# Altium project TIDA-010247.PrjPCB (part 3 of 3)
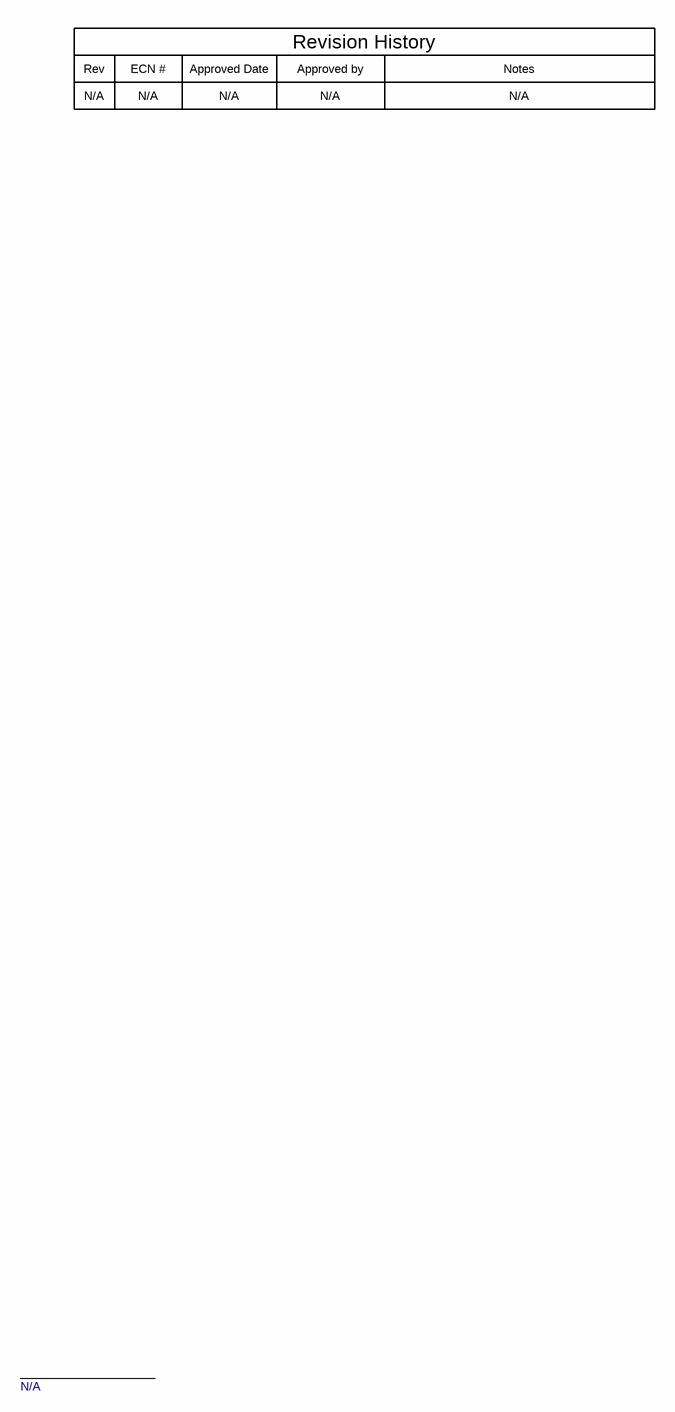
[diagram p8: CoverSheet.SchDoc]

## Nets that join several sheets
GND: High level sch (P7.2 R217.1), Monitor and Cell balancing (37 pins), Aux power (12 pins), MCU and Communication (28 pins), High-side MOSFETs and driver (D26.2 D27.2)
UP_GND: Monitor and Cell balancing (35 pins), High-side MOSFETs and driver (D18.2 D20.2 D23.2)
5V: Monitor and Cell balancing (R120.2), Aux power (R216.2), MCU and Communication (6 pins)
485A: High level sch (P6.1), MCU and Communication (L3.1)
485B: High level sch (P6.2), MCU and Communication (L4.1)
BAT_IN: High level sch (R218.1), Monitor and Cell balancing (D9.2 D12.2), Aux power (D48.2)
BOT_ALERT: Monitor and Cell balancing (U1.25), MCU and Communication (R182.2)
BOT_CB: Monitor and Cell balancing (R113.1), MCU and Communication (U5.7)
BOT_DDSG: High level sch (D49.1), MCU and Communication (D46.1), High-side MOSFETs and driver (R162.1)
BOT_LD: Monitor and Cell balancing (U1.41), High-side MOSFETs and driver (D26.1 D32.2 R169.1)
BOT_PACK: Monitor and Cell balancing (U1.42), High-side MOSFETs and driver (D27.1 R170.1)
BOT_SHUT: Monitor and Cell balancing (C39.1 R110.2 U1.33), MCU and Communication (R183.1)
BOT_WAKE: Monitor and Cell balancing (R87.1), MCU and Communication (U5.36)
BOTAFE_DDSG: High level sch (D49.2), Monitor and Cell balancing (R128.1 U1.32)
CANH: High level sch (P5.2), MCU and Communication (L2.1)
CANL: High level sch (P5.1), MCU and Communication (L1.1)
Cell0: High level sch (P3.1), Monitor and Cell balancing (Q1.2 R21.1)
Cell1: High level sch (P3.2), Monitor and Cell balancing (Q2.2 R1.1 R2.1 R23.1)
Cell2: High level sch (P3.3), Monitor and Cell balancing (Q3.2 R3.1 R4.1 R25.1)
Cell3: High level sch (P3.4), Monitor and Cell balancing (Q4.2 R5.1 R6.1 R27.1)
Cell4: High level sch (P3.5), Monitor and Cell balancing (Q5.2 R7.1 R8.1 R29.1)
Cell5: High level sch (P3.6), Monitor and Cell balancing (Q6.2 R9.1 R10.1 R31.1)
Cell6: High level sch (P3.7), Monitor and Cell balancing (Q7.2 R11.1 R12.1 R33.1)
Cell7: High level sch (P3.8), Monitor and Cell balancing (Q8.2 R13.1 R14.1 R35.1)
Cell8: High level sch (P3.9), Monitor and Cell balancing (Q9.2 R15.1 R16.1 R37.1)
Cell9: High level sch (P3.10), Monitor and Cell balancing (Q10.2 R17.1 R18.1 R39.1)
Cell10: High level sch (P3.11), Monitor and Cell balancing (6 pins)
Cell10B: High level sch (P4.1), Monitor and Cell balancing (Q11.2 R62.1 R63.2 R64.1)
Cell11: High level sch (P4.2), Monitor and Cell balancing (Q12.2 R42.1 R43.1 R66.1)
Cell12: High level sch (P4.3), Monitor and Cell balancing (Q13.2 R44.1 R45.1 R68.1)
Cell13: High level sch (P4.4), Monitor and Cell balancing (Q14.2 R46.1 R47.1 R70.1)
Cell14: High level sch (P4.5), Monitor and Cell balancing (Q15.2 R48.1 R49.1 R72.1)
Cell15: High level sch (P4.6), Monitor and Cell balancing (Q16.2 R50.1 R51.1 R74.1)
Cell16: High level sch (P4.7), Monitor and Cell balancing (Q17.2 R52.1 R53.1 R76.1)
Cell17: High level sch (P4.8), Monitor and Cell balancing (Q18.2 R54.1 R55.1 R78.1)
Cell18: High level sch (P4.9), Monitor and Cell balancing (Q19.2 R56.1 R57.1 R80.1)
Cell19: High level sch (P4.10), Monitor and Cell balancing (Q20.2 R58.1 R59.1 R82.1)
Cell20: High level sch (P4.11 R218.2), Monitor and Cell balancing (R60.1 R61.1 R84.1)
CFETOFF: Monitor and Cell balancing (U1.29), MCU and Communication (R185.2)
Current+: High level sch (5 pins), Monitor and Cell balancing (R103.1), High-side MOSFETs and driver (5 pins)
DET: High level sch (P7.1), MCU and Communication (D38.1)
DFETOFF: Monitor and Cell balancing (U1.30), MCU and Communication (R181.2)
PACK-: High level sch (R219.2 R220.2 R221.2 R222.2), Monitor and Cell balancing (R102.1), High-side MOSFETs and driver (C60.2 D37.2 R173.1)
PWR_EN: Aux power (U9.3), MCU and Communication (R196.1)
SCL: Monitor and Cell balancing (U1.26 U3.3), MCU and Communication (R195.1)
SDA: Monitor and Cell balancing (U1.27 U3.2), MCU and Communication (R192.1)
TOP_ALERT: Monitor and Cell balancing (D15.1 R123.2 R124.2), MCU and Communication (R186.2)
TOP_CHG: Monitor and Cell balancing (U2.45), High-side MOSFETs and driver (R139.1)
TOP_CP1: Monitor and Cell balancing (C29.1 U2.46), High-side MOSFETs and driver (R149.1)
TOP_DSG: Monitor and Cell balancing (U2.43), High-side MOSFETs and driver (R147.2)
TOP_LD: Monitor and Cell balancing (U2.41), High-side MOSFETs and driver (6 pins)
TOP_PDSG: Monitor and Cell balancing (U2.39), High-side MOSFETs and driver (D18.1 R145.1)
TOP_SHUT: Monitor and Cell balancing (Q32.1), MCU and Communication (R180.1)
TOP_WAKE: Monitor and Cell balancing (R85.1), MCU and Communication (U5.31)
VCC1_C: Monitor and Cell balancing (R119.1), MCU and Communication (U5.30)
VCC2_C: Monitor and Cell balancing (R127.1), MCU and Communication (U5.38)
